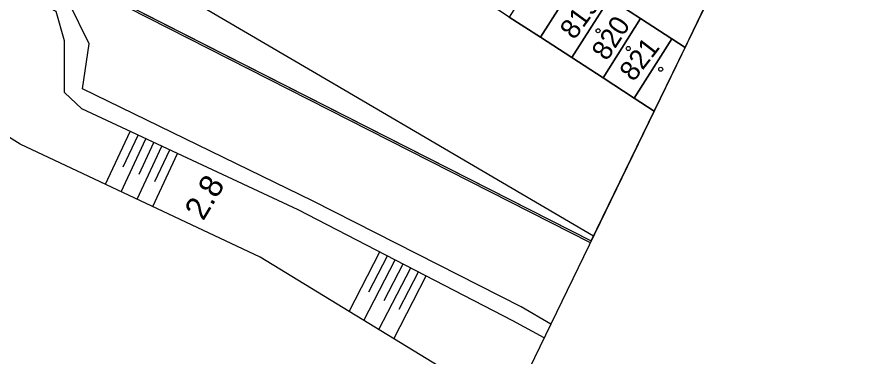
# Model space of a CAD drawing. Extents: x -762314 to -761449, y -993181 to -992589.
# Drawn here: x -761522.3 to -761448.8, y -993015.7 to -992986.5 of the extents above; entities that cross this region are included whole.
import ezdxf

# ---------------------------------------------------------------- set-up
doc = ezdxf.new("R2010")
doc.units = 0
for name, color, linetype in [('Formáty', 7, 'Continuous'), ('Hranice parcel', 7, 'Continuous'), ('Obvody jako plochy', 7, 'Continuous'), ('Parcelní čísla', 7, 'Continuous'), ('Telematika', 7, 'Continuous'), ('Vrstva 23', 7, 'Continuous'), ('Vrstva 48', 7, 'Continuous'), ('Vrstva 49', 7, 'Continuous'), ('Vrstva 53', 7, 'Continuous'), ('Značky na budově v SPI', 7, 'Continuous')]:
    doc.layers.add(name, color=color, linetype=linetype)

msp = doc.modelspace()

# ---------------------------------------------------------------- linework, layer by layer
at = {"layer": 'Formáty'}
msp.add_lwpolyline([(-761558.019, -993180.938), (-762313.703, -992814.139), (-762204.471, -992589.097), (-761448.787, -992955.896)], close=True, dxfattribs=at)
msp.add_lwpolyline([(-761558.019, -993180.938), (-762313.703, -992814.139), (-762204.471, -992589.097), (-761448.787, -992955.896)], close=True, dxfattribs=at)
at = {"layer": 'Hranice parcel'}
for p, q in [((-761546.355, -992968.446), (-761472.992, -993005.764)), ((-761477.335, -992988.276), (-761474.105, -992983.176)), ((-761471.415, -992984.926), (-761474.655, -992990.016)), ((-761468.735, -992986.666), (-761471.415, -992984.926)), ((-761480.015, -992986.536), (-761477.335, -992988.276)), ((-761471.965, -992991.766), (-761468.735, -992986.666)), ((-761466.055, -992988.406), (-761468.735, -992986.666)), ((-761477.335, -992988.276), (-761474.655, -992990.016)), ((-761466.055, -992988.406), (-761469.285, -992993.506)), ((-761466.055, -992988.406), (-761464.922, -992989.138)), ((-761474.655, -992990.016), (-761471.965, -992991.766)), ((-761471.965, -992991.766), (-761469.285, -992993.506)), ((-761469.285, -992993.506), (-761467.582, -992994.618))]:
    msp.add_line(p, q, dxfattribs=at)
at = {"layer": 'Obvody jako plochy'}
for p, q in [((-761464.922, -992989.138), (-761460.067, -992979.136)), ((-761477.335, -992988.276), (-761474.105, -992983.176)), ((-761477.335, -992988.276), (-761474.105, -992983.176)), ((-761471.415, -992984.926), (-761474.655, -992990.016)), ((-761471.415, -992984.926), (-761474.655, -992990.016)), ((-761468.735, -992986.666), (-761471.415, -992984.926)), ((-761480.015, -992986.536), (-761477.335, -992988.276)), ((-761471.965, -992991.766), (-761468.735, -992986.666)), ((-761471.965, -992991.766), (-761468.735, -992986.666)), ((-761466.055, -992988.406), (-761468.735, -992986.666)), ((-761477.335, -992988.276), (-761474.655, -992990.016)), ((-761466.055, -992988.406), (-761469.285, -992993.506)), ((-761466.055, -992988.406), (-761469.285, -992993.506)), ((-761466.055, -992988.406), (-761464.922, -992989.138)), ((-761467.582, -992994.618), (-761464.922, -992989.138)), ((-761467.582, -992994.618), (-761464.922, -992989.138)), ((-761474.655, -992990.016), (-761471.965, -992991.766)), ((-761471.965, -992991.766), (-761469.285, -992993.506)), ((-761469.285, -992993.506), (-761467.582, -992994.618)), ((-761472.992, -993005.764), (-761467.582, -992994.618))]:
    msp.add_line(p, q, dxfattribs=at)
for points in [[(-761516.401, -992923.077), (-761522.385, -992932.146), (-761535.005, -992951.256), (-761546.355, -992968.446), (-761472.992, -993005.764)], [(-761467.582, -992994.618), (-761469.285, -992993.506), (-761471.965, -992991.766), (-761474.655, -992990.016), (-761477.335, -992988.276), (-761480.015, -992986.536), (-761482.695, -992984.786), (-761485.385, -992983.046), (-761488.085, -992981.336), (-761484.855, -992976.246), (-761482.155, -992977.946), (-761479.465, -992979.696), (-761476.785, -992981.436), (-761474.105, -992983.176), (-761471.415, -992984.926), (-761468.735, -992986.666), (-761466.055, -992988.406), (-761464.922, -992989.138)], [(-761464.922, -992989.138), (-761466.055, -992988.406), (-761469.285, -992993.506), (-761467.582, -992994.618)], [(-761464.922, -992989.138), (-761466.055, -992988.406), (-761469.285, -992993.506), (-761467.582, -992994.618)]]:
    msp.add_lwpolyline(points, dxfattribs=at)
for points in [[(-761474.105, -992983.176), (-761476.785, -992981.436), (-761480.015, -992986.536), (-761477.335, -992988.276)], [(-761474.105, -992983.176), (-761476.785, -992981.436), (-761480.015, -992986.536), (-761477.335, -992988.276)], [(-761471.415, -992984.926), (-761474.105, -992983.176), (-761477.335, -992988.276), (-761474.655, -992990.016)], [(-761477.335, -992988.276), (-761474.655, -992990.016), (-761471.415, -992984.926), (-761474.105, -992983.176)], [(-761468.735, -992986.666), (-761471.415, -992984.926), (-761474.655, -992990.016), (-761471.965, -992991.766)], [(-761474.655, -992990.016), (-761471.965, -992991.766), (-761468.735, -992986.666), (-761471.415, -992984.926)], [(-761466.055, -992988.406), (-761468.735, -992986.666), (-761471.965, -992991.766), (-761469.285, -992993.506)], [(-761471.965, -992991.766), (-761468.735, -992986.666), (-761466.055, -992988.406), (-761469.285, -992993.506)]]:
    msp.add_lwpolyline(points, close=True, dxfattribs=at)
at = {"layer": 'Telematika'}
msp.add_lwpolyline([(-761756.252, -992833.564), (-761749.977, -992832.673), (-761744.065, -992831.129), (-761739.379, -992828.495), (-761724.281, -992841.754), (-761712.868, -992849.407), (-761696.881, -992847.078), (-761688.903, -992861.107), (-761670.259, -992871.026), (-761666.21, -992870.265), (-761659.894, -992885.192), (-761661.564, -992897.197), (-761654.833, -992905.136), (-761643.955, -992914.725), (-761586.887, -992944.777), (-761514.007, -992981.167), (-761495.067, -992992.268), (-761472.782, -993005.331)], dxfattribs=at)
at = {"layer": 'Vrstva 23'}
msp.add_lwpolyline([(-761476.458, -993012.905), (-761479.008, -993011.431), (-761496.849, -993002.358), (-761516.679, -992992.713), (-761516.096, -992988.85), (-761517.847, -992985.289), (-761536.085, -992976.525), (-761588.131, -992951.527)], dxfattribs=at)
at = {"layer": 'Vrstva 48'}
for p, q in [((-761514.7, -993000.895), (-761512.58, -992996.352)), ((-761513.173, -992999.396), (-761511.9, -992996.669)), ((-761513.343, -993001.534), (-761511.221, -992996.986)), ((-761511.986, -993002.173), (-761509.861, -992997.62)), ((-761511.815, -993000.033), (-761510.541, -992997.303)), ((-761510.628, -993002.812), (-761508.502, -992998.254)), ((-761510.457, -993000.67), (-761509.182, -992997.937)), ((-761493.778, -993011.809), (-761491.141, -993006.704)), ((-761492.072, -993010.139), (-761490.475, -993007.048)), ((-761492.494, -993012.592), (-761489.808, -993007.392)), ((-761490.768, -993010.885), (-761489.142, -993007.736)), ((-761491.21, -993013.376), (-761488.476, -993008.08)), ((-761489.465, -993011.63), (-761487.809, -993008.424)), ((-761489.927, -993014.159), (-761487.143, -993008.769))]:
    msp.add_line(p, q, dxfattribs=at)
at = {"layer": 'Vrstva 49'}
msp.add_line((-761522.035, -992997.443), (-761566.245, -992970.466), dxfattribs=at)
for points in [[(-761479.709, -993012.608), (-761498.134, -993003.092), (-761516.722, -992994.419), (-761518.227, -992993.007), (-761518.206, -992988.59), (-761518.945, -992986.061), (-761536.188, -992977.331), (-761586.59, -992953.804)], [(-761479.866, -993019.927), (-761482.23, -993018.856), (-761501.416, -993007.148), (-761522.035, -992997.443)], [(-761477.027, -993014.077), (-761479.709, -993012.608)]]:
    msp.add_lwpolyline(points, dxfattribs=at)
at = {"layer": 'Vrstva 53'}
msp.add_line((-761546.386, -992968.612), (-761473.06, -993005.905), dxfattribs=at)
at = {"layer": 'Značky na budově v SPI'}
for centre in [(-761472.385, -992987.716), (-761469.795, -992989.236), (-761467.005, -992991.016)]:
    msp.add_circle(centre, 0.175, dxfattribs=at)

# ---------------------------------------------------------------- texts
at = {"layer": 'Parcelní čísla'}
for s, rotation, p in [('819', 53.91495, (-761474.425, -992988.556)), ('820', 57.09474, (-761471.625, -992990.376)), ('821', 52.20603, (-761469.345, -992992.156))]:
    msp.add_text(s, height=1.7, rotation=rotation, dxfattribs=at).set_placement(p)
at = {"layer": 'Vrstva 48'}
msp.add_text('2.8', height=2, rotation=59.15828, dxfattribs=at).set_placement((-761506.3, -993004.102))

doc.saveas('drawing.dxf')
